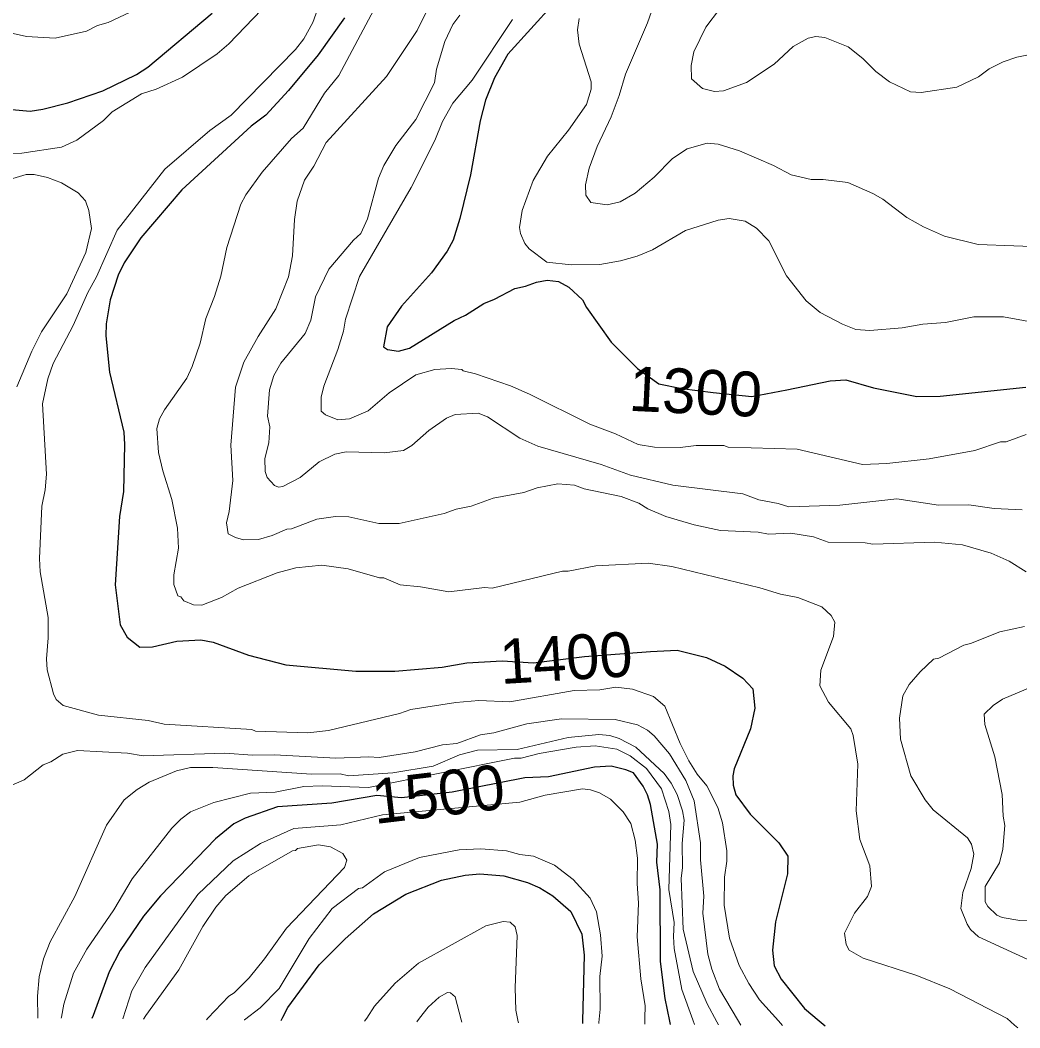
# Model space of a CAD drawing. Extents: x 598.3 to 623.2, y 6902.2 to 6930.1.
# Drawn here: x 619.57 to 621.358, y 6902.173 to 6903.976 of the extents above; entities that cross this region are included whole.
import ezdxf
from ezdxf.enums import TextEntityAlignment as Align

# ---------------------------------------------------------------- set-up
doc = ezdxf.new("R2010")
doc.units = 0
doc.header["$LTSCALE"] = 0.032
doc.layers.add('1', color=7, linetype='Continuous', lineweight=25)
doc.layers.add('2', color=7, linetype='Continuous', lineweight=13)
doc.layers.add('61', color=7, linetype='Continuous')

msp = doc.modelspace()

# ---------------------------------------------------------------- linework, layer by layer
at = {"layer": '1'}
for points in [[(620.5245, 6904.0059), (620.4421, 6903.9155), (620.4184, 6903.8728), (620.4022, 6903.8332), (620.3929, 6903.796), (620.3752, 6903.6993), (620.3564, 6903.6211), (620.3445, 6903.5827), (620.3339, 6903.5629), (620.3056, 6903.524), (620.2517, 6903.4644), (620.2261, 6903.4274), (620.2197, 6903.3918), (620.2271, 6903.3869), (620.2468, 6903.3837), (620.266, 6903.3895), (620.3463, 6903.4389), (620.3667, 6903.4483), (620.3991, 6903.4694), (620.4181, 6903.4772), (620.4546, 6903.4963), (620.474, 6903.5003), (620.4935, 6903.5076), (620.5129, 6903.5107), (620.5327, 6903.5088), (620.5515, 6903.4986), (620.5757, 6903.4759), (620.5832, 6903.462), (620.6274, 6903.4002), (620.6745, 6903.3529), (620.7126, 6903.3255), (620.7534, 6903.3173), (620.8095, 6903.3102), (620.8786, 6903.3029), (620.9413, 6903.315), (621.0193, 6903.331), (621.0468, 6903.3327), (621.0967, 6903.3182), (621.1741, 6903.3028), (621.216, 6903.3037), (621.3693, 6903.3198)], [(619.5221, 6903.8191), (619.5873, 6903.8136), (619.61, 6903.8169), (619.6548, 6903.8281), (619.7174, 6903.8498), (619.7779, 6903.8792), (619.7981, 6903.8922), (619.9131, 6903.9888)], [(620.1501, 6903.9806), (620.1028, 6903.9141), (620.0498, 6903.8501), (620.0089, 6903.8061), (619.983, 6903.7866), (619.8591, 6903.6724), (619.7855, 6903.5866), (619.7559, 6903.5418), (619.7451, 6903.5202), (619.7308, 6903.4759), (619.7233, 6903.4327), (619.7226, 6903.4113), (619.7297, 6903.3464), (619.7549, 6903.2391), (619.7565, 6903.2169), (619.7542, 6903.1326), (619.7476, 6903.0879), (619.7397, 6902.9656), (619.7484, 6902.8942), (619.7612, 6902.8724), (619.7836, 6902.8543), (619.8064, 6902.855), (619.8502, 6902.865), (619.8928, 6902.8672), (619.9149, 6902.8632), (619.978, 6902.8398), (620.045, 6902.8227), (620.17, 6902.8116), (620.2399, 6902.8115), (620.3245, 6902.8186), (620.3688, 6902.826), (620.432, 6902.83), (620.4881, 6902.826), (620.5797, 6902.8374), (620.6975, 6902.8467), (620.7452, 6902.8488), (620.798, 6902.836)], [(620.798, 6902.836), (620.8313, 6902.8204), (620.8626, 6902.7989), (620.8804, 6902.7797), (620.8841, 6902.7453), (620.8764, 6902.7081), (620.847, 6902.6364), (620.8446, 6902.6239), (620.8453, 6902.6077), (620.8501, 6902.5899), (620.876, 6902.5555), (620.9269, 6902.504), (620.9431, 6902.4804), (620.9424, 6902.4487), (620.9214, 6902.3629), (620.9158, 6902.312), (620.9189, 6902.2839), (620.9315, 6902.2603), (620.9729, 6902.2077), (620.9992, 6902.1857), (621.01, 6902.1766)], [(620.7333, 6902.1794), (620.7322, 6902.185), (620.7239, 6902.2256), (620.7156, 6902.292), (620.7149, 6902.4199), (620.7086, 6902.4694), (620.7101, 6902.5021), (620.6973, 6902.5727), (620.6922, 6902.5899), (620.6844, 6902.6055), (620.6672, 6902.6292), (620.6534, 6902.635), (620.6269, 6902.6414), (620.5971, 6902.6398), (620.5149, 6902.6223), (620.4729, 6902.6203), (620.3424, 6902.5946), (620.2521, 6902.5849), (620.2081, 6902.589), (620.127, 6902.575), (620.0301, 6902.5685), (619.9719, 6902.5482), (619.9518, 6902.5381), (619.919, 6902.5116), (619.8207, 6902.4093), (619.79, 6902.3728), (619.7488, 6902.3118), (619.7289, 6902.2735), (619.7, 6902.1954), (619.6979, 6902.1898)], [(620.0368, 6902.1864), (620.0397, 6902.1921), (620.0487, 6902.2097), (620.1044, 6902.2858), (620.1509, 6902.3324), (620.2021, 6902.3769), (620.2598, 6902.4121), (620.3235, 6902.4374), (620.3658, 6902.4466), (620.392, 6902.4487), (620.4349, 6902.4454), (620.4773, 6902.4332), (620.4996, 6902.4236), (620.5226, 6902.4096), (620.5549, 6902.3813), (620.5749, 6902.3407), (620.579, 6902.3033), (620.5758, 6902.1857), (620.5757, 6902.181)]]:
    msp.add_lwpolyline(points, dxfattribs=at)
at = {"layer": '2'}
for points in [[(620.1314, 6904.0791), (620.0932, 6903.9722), (620.077, 6903.9428), (620.0625, 6903.9237), (619.9469, 6903.8064), (619.9092, 6903.779), (619.8283, 6903.7096), (619.7434, 6903.6003), (619.7061, 6903.5167), (619.6904, 6903.4887), (619.6642, 6903.4298), (619.6285, 6903.3616), (619.619, 6903.3346), (619.6096, 6903.2895), (619.6165, 6903.1638), (619.6141, 6903.1357), (619.6085, 6903.1066), (619.6043, 6903.0132), (619.6052, 6902.9889), (619.6197, 6902.9075), (619.6197, 6902.8708), (619.6166, 6902.8334), (619.618, 6902.814), (619.629, 6902.7707), (619.6341, 6902.7605), (619.6468, 6902.7497), (619.7096, 6902.7329), (619.7986, 6902.7231), (619.8272, 6902.7165), (619.9844, 6902.707), (619.9909, 6902.7038), (620.0846, 6902.7013), (620.1215, 6902.7051), (620.2481, 6902.7354)], [(620.724, 6904.0614), (620.6919, 6903.9715), (620.6525, 6903.8797), (620.6415, 6903.8416), (620.6271, 6903.8032), (620.6022, 6903.7499), (620.5878, 6903.7113), (620.5813, 6903.6815), (620.5815, 6903.663), (620.5905, 6903.6501), (620.6201, 6903.646), (620.6431, 6903.6512), (620.6701, 6903.6665), (620.7038, 6903.6955), (620.7371, 6903.7289), (620.7633, 6903.7461), (620.7992, 6903.756), (620.8186, 6903.7544), (620.8569, 6903.7425), (620.9179, 6903.7161), (620.9493, 6903.6995), (620.9848, 6903.6913), (621.0067, 6903.6912), (621.0509, 6903.6856), (621.0953, 6903.6662), (621.113, 6903.6558), (621.156, 6903.6231), (621.1861, 6903.6062), (621.2234, 6903.5897), (621.2838, 6903.5749), (621.4117, 6903.5699)], [(619.269, 6903.9973), (619.322, 6903.9761), (619.3474, 6903.9587), (619.3817, 6903.9239), (619.4016, 6903.91), (619.4155, 6903.9099), (619.431, 6903.9131), (619.4442, 6903.923), (619.4656, 6903.945), (619.4919, 6903.9608), (619.5135, 6903.9617), (619.5812, 6903.9471), (619.6325, 6903.9439), (619.6883, 6903.9567), (619.708, 6903.9665), (619.7272, 6903.972), (619.7765, 6903.9952)], [(619.435, 6903.7334), (619.5726, 6903.7383), (619.6436, 6903.7488), (619.671, 6903.7613), (619.7189, 6903.7969), (619.7342, 6903.8121), (619.7865, 6903.8442), (619.813, 6903.853), (619.86, 6903.8741), (619.9219, 6903.9157), (619.9427, 6903.934), (620.0014, 6903.9945)], [(620.2025, 6903.9948), (620.14, 6903.8774), (620.1144, 6903.8453), (620.0759, 6903.7832), (620.0554, 6903.7643), (620.0027, 6903.7042), (619.9735, 6903.6636), (619.9646, 6903.647), (619.9395, 6903.5693), (619.9287, 6903.5179), (619.9176, 6903.4816), (619.9021, 6903.4423), (619.8915, 6903.3981)], [(621.3769, 6903.9147), (621.3531, 6903.9099), (621.3286, 6903.9017), (621.3038, 6903.8889), (621.2846, 6903.8749), (621.2455, 6903.8563), (621.1818, 6903.8468), (621.1628, 6903.8481), (621.1254, 6903.8659), (621.1009, 6903.8841), (621.0773, 6903.9078), (621.0512, 6903.9287), (621.0097, 6903.9453), (620.9934, 6903.947), (620.9798, 6903.9438), (620.9528, 6903.9291), (620.9188, 6903.8975), (620.8691, 6903.8647), (620.8283, 6903.85), (620.8119, 6903.8484), (620.7905, 6903.8542), (620.7709, 6903.8711), (620.7701, 6903.8953), (620.7752, 6903.9196), (620.7966, 6903.9639), (620.8211, 6903.9957)], [(620.2954, 6903.9895), (620.2801, 6903.9574), (620.2249, 6903.8753), (620.1172, 6903.757), (620.0952, 6903.7152), (620.0785, 6903.69), (620.0655, 6903.6523), (620.0602, 6903.6198), (620.0568, 6903.5543), (620.0496, 6903.5172), (620.0272, 6903.4594), (619.9953, 6903.4104), (619.9698, 6903.3643), (619.9549, 6903.3193), (619.9467, 6903.2157), (619.95, 6903.1525), (619.9436, 6903.0969), (619.9387, 6903.0765), (619.9419, 6903.0571), (619.9548, 6903.0505), (619.9692, 6903.0466), (619.9959, 6903.0469), (620.0207, 6903.0543), (620.0466, 6903.0655), (620.0554, 6903.0659), (620.1005, 6903.0831), (620.1336, 6903.0882), (620.1578, 6903.0875), (620.2113, 6903.0753), (620.2477, 6903.0753), (620.3282, 6903.0934), (620.3497, 6903.1013), (620.3769, 6903.1069), (620.4162, 6903.1212), (620.4708, 6903.1312), (620.4946, 6903.1392), (620.5314, 6903.1466), (620.5618, 6903.1441), (620.5788, 6903.1376), (620.6452, 6903.1239), (620.6767, 6903.1117), (620.6926, 6903.1017), (620.7248, 6903.0884), (620.7759, 6903.0733), (620.8229, 6903.0632), (620.8901, 6903.0598), (620.9084, 6903.0567), (620.9487, 6903.0582), (620.9891, 6903.0518), (621.0156, 6903.0421), (621.0815, 6903.0412), (621.0955, 6903.0388), (621.2056, 6903.0421), (621.2557, 6903.0372), (621.3073, 6903.0227)], [(620.3562, 6903.9849), (620.3441, 6903.9687), (620.3293, 6903.9378), (620.3143, 6903.8883), (620.311, 6903.8638), (620.2777, 6903.7987), (620.2416, 6903.7519), (620.2201, 6903.7159), (620.211, 6903.6935), (620.1912, 6903.6208), (620.179, 6903.5942), (620.1661, 6903.5827), (620.1221, 6903.5305), (620.098, 6903.4814), (620.09, 6903.4393), (620.0798, 6903.4157), (620.0362, 6903.3623), (620.0236, 6903.3405), (620.0156, 6903.3145), (620.0124, 6903.2677), (620.0164, 6903.2483), (620.0148, 6903.2199), (620.0076, 6903.1921), (620.0082, 6903.1684), (620.0116, 6903.158), (620.0244, 6903.1435), (620.0321, 6903.1409), (620.0397, 6903.1416)], [(621.3696, 6903.2349), (621.3339, 6903.2218), (621.3237, 6903.2217), (621.2779, 6903.2063), (621.1959, 6903.1912), (621.1203, 6903.183), (621.0771, 6903.1814), (620.9597, 6903.2088), (620.8365, 6903.2121), (620.8285, 6903.2154), (620.7795, 6903.2153), (620.7507, 6903.2113), (620.7047, 6903.2121), (620.6755, 6903.2167), (620.6346, 6903.2361), (620.5887, 6903.2533), (620.4808, 6903.3073), (620.4468, 6903.3219), (620.3845, 6903.3433), (620.3625, 6903.3487), (620.3601, 6903.3513), (620.341, 6903.353), (620.3118, 6903.3513), (620.2778, 6903.3415), (620.2296, 6903.3096), (620.1921, 6903.277), (620.1591, 6903.2629), (620.1381, 6903.2608), (620.116, 6903.2699), (620.1079, 6903.2763), (620.1079, 6903.3019), (620.1128, 6903.3216), (620.138, 6903.3867), (620.1482, 6903.4196), (620.1516, 6903.4414), (620.1765, 6903.5173), (620.2692, 6903.6765), (620.3115, 6903.7611), (620.3251, 6903.7947), (620.3439, 6903.8276), (620.3784, 6903.8688), (620.4504, 6903.9776)], [(621.4009, 6903.4323), (621.3289, 6903.4452), (621.2758, 6903.4453), (621.2252, 6903.4355), (621.1848, 6903.4323), (621.1478, 6903.4258), (621.0899, 6903.421), (621.0648, 6903.4226), (621.0409, 6903.432), (621.0012, 6903.4529), (620.976, 6903.474), (620.9408, 6903.5188), (620.9094, 6903.5812), (620.8872, 6903.604), (620.867, 6903.6168), (620.8381, 6903.6216), (620.8184, 6903.6184), (620.7601, 6903.5997), (620.7013, 6903.5655), (620.6734, 6903.5541), (620.6437, 6903.5455), (620.6071, 6903.5392), (620.5554, 6903.5384), (620.5119, 6903.5431), (620.4806, 6903.5671), (620.4728, 6903.5765), (620.465, 6903.5944), (620.4633, 6903.6055), (620.4681, 6903.6357), (620.4878, 6903.6894), (620.5131, 6903.7328), (620.551, 6903.7792), (620.5832, 6903.8254), (620.5912, 6903.853), (620.5912, 6903.8659), (620.5696, 6903.9332), (620.5668, 6903.9586), (620.5701, 6903.9789)], [(619.5639, 6903.32), (619.5904, 6903.384), (619.6075, 6903.4183), (619.6529, 6903.4866), (619.6873, 6903.5603), (619.6974, 6903.6036), (619.6926, 6903.6357), (619.6862, 6903.6531), (619.6732, 6903.667), (619.6438, 6903.6854), (619.6187, 6903.6946), (619.5946, 6903.7001), (619.5804, 6903.7002), (619.5302, 6903.6849)], [(619.8915, 6903.3981), (619.8775, 6903.3563), (619.8681, 6903.3357), (619.8276, 6903.279), (619.8188, 6903.2627), (619.8141, 6903.2455), (619.8173, 6903.2029), (619.8247, 6903.1697), (619.8409, 6903.1185), (619.8512, 6903.0674), (619.8528, 6903.0313), (619.8447, 6902.984), (619.8448, 6902.9666), (619.852, 6902.946), (619.8568, 6902.9441), (619.8624, 6902.9374), (619.8799, 6902.9303), (619.8944, 6902.9296), (619.9301, 6902.9434), (619.9598, 6902.9599), (620.0294, 6902.9873), (620.0628, 6902.996), (620.1091, 6903.0009), (620.1567, 6902.9943), (620.2128, 6902.9783), (620.2202, 6902.9781), (620.2497, 6902.9657), (620.2857, 6902.962), (620.3364, 6902.9531), (620.4007, 6902.9611), (620.4144, 6902.9596), (620.5401, 6902.9902), (620.5504, 6902.9903), (620.5998, 6902.9999), (620.6935, 6903.0049), (620.7358, 6902.9984), (620.8934, 6902.9603), (620.9303, 6902.9489), (620.9609, 6902.9434), (621.004, 6902.9263), (621.021, 6902.9107), (621.0275, 6902.8991), (621.0252, 6902.8735), (621.0024, 6902.8133), (621.0008, 6902.7852), (621.0158, 6902.7561), (621.0558, 6902.7082), (621.0599, 6902.6962), (621.0687, 6902.6452), (621.0656, 6902.5614), (621.072, 6902.51), (621.0897, 6902.4633), (621.093, 6902.4263), (621.0856, 6902.408), (621.0624, 6902.3782), (621.0444, 6902.3424), (621.0474, 6902.3225), (621.0532, 6902.3122), (621.0779, 6902.298), (621.1739, 6902.2669), (621.2333, 6902.243), (621.3356, 6902.1898), (621.349, 6902.1777), (621.3546, 6902.1732)], [(620.0397, 6903.1416), (620.0704, 6903.1577), (620.1044, 6903.186), (620.1329, 6903.1997), (620.153, 6903.2039), (620.2208, 6903.2023), (620.2554, 6903.2064), (620.2702, 6903.215), (620.3011, 6903.2419), (620.3326, 6903.2641), (620.3481, 6903.2704), (620.3891, 6903.2728), (620.4057, 6903.2662), (620.4635, 6903.2285), (620.4959, 6903.2139), (620.6095, 6903.1814), (620.6615, 6903.1618), (620.7374, 6903.1441), (620.8626, 6903.1288), (620.8912, 6903.1182), (620.9257, 6903.1116), (620.9453, 6903.1053), (621.0361, 6903.1085), (621.1385, 6903.1198), (621.2131, 6903.1085), (621.267, 6903.1092), (621.3127, 6903.1023), (621.3626, 6903.1003)], [(621.3073, 6903.0227), (621.3394, 6903.0083), (621.3698, 6902.989)], [(621.3669, 6902.8914), (621.3229, 6902.8817), (621.2701, 6902.8607), (621.2582, 6902.858), (621.2136, 6902.8349), (621.2039, 6902.833), (621.1798, 6902.8099), (621.1605, 6902.7874), (621.1488, 6902.7674), (621.1432, 6902.7271), (621.1449, 6902.6897), (621.1631, 6902.6242), (621.1888, 6902.5811), (621.2035, 6902.5633), (621.265, 6902.513), (621.272, 6902.5019), (621.2759, 6902.4841), (621.2711, 6902.4585), (621.2562, 6902.4154), (621.2526, 6902.3865), (621.264, 6902.3585), (621.2703, 6902.3492), (621.2843, 6902.3358), (621.3728, 6902.2955)], [(620.2481, 6902.7354), (620.2684, 6902.7426), (620.3491, 6902.7555), (620.3902, 6902.7588), (620.4459, 6902.7567), (620.561, 6902.7765), (620.6071, 6902.7782), (620.6356, 6902.783), (620.6651, 6902.779), (620.7031, 6902.7663), (620.7234, 6902.7485), (620.7508, 6902.6818), (620.7661, 6902.6509), (620.781, 6902.6273), (620.7984, 6902.606), (620.8181, 6902.5676), (620.8266, 6902.54), (620.8339, 6902.4898), (620.8339, 6902.4712), (620.83, 6902.4428), (620.8292, 6902.3928), (620.8389, 6902.3336), (620.8561, 6902.2847), (620.8733, 6902.2524), (620.8926, 6902.2233), (620.9263, 6902.1857), (620.9338, 6902.1774)], [(621.3811, 6902.784), (621.3274, 6902.7614), (621.3108, 6902.7498), (621.2946, 6902.7344), (621.2959, 6902.7162), (621.3139, 6902.6581), (621.327, 6902.591), (621.3286, 6902.5518), (621.3317, 6902.5351), (621.3278, 6902.4927), (621.322, 6902.4682), (621.2963, 6902.4263), (621.2962, 6902.3988), (621.3012, 6902.3902), (621.3172, 6902.3751), (621.3266, 6902.3709), (621.3584, 6902.3654), (621.473, 6902.3621)], [(620.8589, 6902.1781), (620.8529, 6902.1884), (620.8212, 6902.2427), (620.8075, 6902.2779), (620.7999, 6902.3049), (620.7911, 6902.3782), (620.7928, 6902.409), (620.7871, 6902.4741), (620.787, 6902.5043), (620.7758, 6902.5796), (620.761, 6902.6158), (620.7315, 6902.6636), (620.7041, 6902.6959), (620.6919, 6902.7057), (620.6743, 6902.7151), (620.634, 6902.7247), (620.5385, 6902.7263), (620.4765, 6902.7173), (620.4174, 6902.7013), (620.3931, 6902.6973), (620.3512, 6902.6819), (620.3251, 6902.6795), (620.2765, 6902.6673), (620.2121, 6902.6568), (620.1937, 6902.6583), (620.1345, 6902.656), (620.0249, 6902.6617), (619.9855, 6902.6609), (619.9359, 6902.6649), (619.7896, 6902.6599), (619.7617, 6902.6648), (619.6722, 6902.6697), (619.6462, 6902.6631), (619.6243, 6902.6489), (619.611, 6902.6439), (619.5766, 6902.6169), (619.5534, 6902.6069)], [(620.8192, 6902.1785), (620.8162, 6902.1841), (620.7987, 6902.2164), (620.7739, 6902.2742), (620.7562, 6902.3499), (620.7522, 6902.4402), (620.7546, 6902.4598), (620.7539, 6902.503), (620.7578, 6902.5448), (620.7548, 6902.5615), (620.7452, 6902.5907), (620.7343, 6902.6109), (620.7218, 6902.628), (620.6711, 6902.6755), (620.6412, 6902.6911), (620.6249, 6902.6963), (620.6049, 6902.6981), (620.5501, 6902.6924), (620.4592, 6902.6714), (620.3882, 6902.6698), (620.3556, 6902.6616), (620.3089, 6902.6414), (620.2366, 6902.6293), (620.1571, 6902.6244), (620.1419, 6902.6276), (620.0908, 6902.6269), (619.9142, 6902.6389), (619.8745, 6902.6389), (619.8491, 6902.6333), (619.8007, 6902.6125), (619.7791, 6902.5997), (619.7554, 6902.581), (619.7239, 6902.5356), (619.6675, 6902.4082), (619.6235, 6902.3268), (619.6113, 6902.2966), (619.6036, 6902.2647), (619.6003, 6902.2298), (619.6012, 6902.1908)], [(620.7765, 6902.179), (620.7734, 6902.1873), (620.7533, 6902.2421), (620.7401, 6902.3154), (620.7385, 6902.3369), (620.74, 6902.3619), (620.7303, 6902.4205), (620.7337, 6902.5371), (620.7303, 6902.5604), (620.7174, 6902.6009), (620.6903, 6902.637), (620.6613, 6902.6601), (620.6375, 6902.6721), (620.5984, 6902.6778), (620.5642, 6902.6753), (620.4983, 6902.6641), (620.4659, 6902.656), (620.4541, 6902.6555), (620.1926, 6902.6034), (620.1098, 6902.6065), (620.0771, 6902.6049), (620.026, 6902.5951), (619.9819, 6902.5929), (619.9159, 6902.5764), (619.8745, 6902.5595), (619.8569, 6902.5466), (619.8409, 6902.5306), (619.77, 6902.4401), (619.7373, 6902.3842), (619.689, 6902.3138), (619.6651, 6902.2709), (619.6476, 6902.2153), (619.6433, 6902.1922), (619.643, 6902.1903)], [(619.7535, 6902.1892), (619.7694, 6902.2397), (619.7931, 6902.2809), (619.8877, 6902.4115), (619.951, 6902.4723), (619.9999, 6902.5032), (620.0593, 6902.5296), (620.1435, 6902.5362), (620.218, 6902.5546), (620.4635, 6902.5767), (620.5092, 6902.5895), (620.5761, 6902.601), (620.5901, 6902.5993), (620.6062, 6902.5937), (620.6259, 6902.5822), (620.6488, 6902.5594), (620.6624, 6902.5389), (620.6703, 6902.5092), (620.6745, 6902.4768), (620.6737, 6902.4316), (620.6762, 6902.3964), (620.6738, 6902.3361), (620.6801, 6902.2609), (620.6882, 6902.2126), (620.6875, 6902.1906), (620.6872, 6902.1799)], [(619.9029, 6902.1878), (619.9056, 6902.1906), (619.9431, 6902.2297), (619.9523, 6902.2357), (619.9792, 6902.2627), (620.0068, 6902.2967), (620.0464, 6902.3516), (620.1498, 6902.4599), (620.1539, 6902.4734), (620.1467, 6902.4851), (620.1248, 6902.4973), (620.1036, 6902.5006), (620.0656, 6902.4942), (620.0621, 6902.4905), (620.057, 6902.49), (619.9788, 6902.4449), (619.9375, 6902.4102), (619.92, 6902.3894), (619.8965, 6902.3548), (619.8535, 6902.2769), (619.7947, 6902.1954), (619.79, 6902.1889)], [(620.6048, 6902.1807), (620.605, 6902.1825), (620.6074, 6902.2069), (620.6066, 6902.2651), (620.6113, 6902.3017), (620.6082, 6902.3397), (620.6008, 6902.3807), (620.5895, 6902.405), (620.5591, 6902.4385), (620.5256, 6902.4641), (620.4881, 6902.4803), (620.4638, 6902.4836), (620.44, 6902.49), (620.394, 6902.4933), (620.3554, 6902.4916), (620.284, 6902.4779), (620.2217, 6902.4522), (620.1819, 6902.424), (620.1752, 6902.4224), (620.1278, 6902.3867), (620.0868, 6902.3329), (620.0329, 6902.2436), (619.9988, 6902.2093), (619.9711, 6902.1873), (619.9708, 6902.1871)], [(620.4613, 6902.1822), (620.4609, 6902.1841), (620.4563, 6902.2046), (620.4553, 6902.2448), (620.4591, 6902.3386), (620.4551, 6902.3538), (620.4464, 6902.3622), (620.4339, 6902.3637), (620.4028, 6902.3558), (620.2825, 6902.2891), (620.2409, 6902.2531), (620.2036, 6902.2117), (620.1897, 6902.1906), (620.186, 6902.1849)], [(620.36, 6902.1832), (620.3589, 6902.1873), (620.3477, 6902.2288), (620.3396, 6902.2357), (620.3341, 6902.2365), (620.3192, 6902.2279), (620.2994, 6902.2103), (620.2844, 6902.1906), (620.2794, 6902.184)]]:
    msp.add_lwpolyline(points, dxfattribs=at)

# ---------------------------------------------------------------- texts
at = {"layer": '61'}
for s, rotation, p in [('1300', 357.248, (620.7764, 6903.2717)), ('1400', 3.468, (620.5488, 6902.7955)), ('1500', 6.843, (620.3224, 6902.5519))]:
    msp.add_text(s, height=0.08, rotation=rotation, dxfattribs=at).set_placement(p, align=Align.CENTER)

doc.saveas('drawing.dxf')
